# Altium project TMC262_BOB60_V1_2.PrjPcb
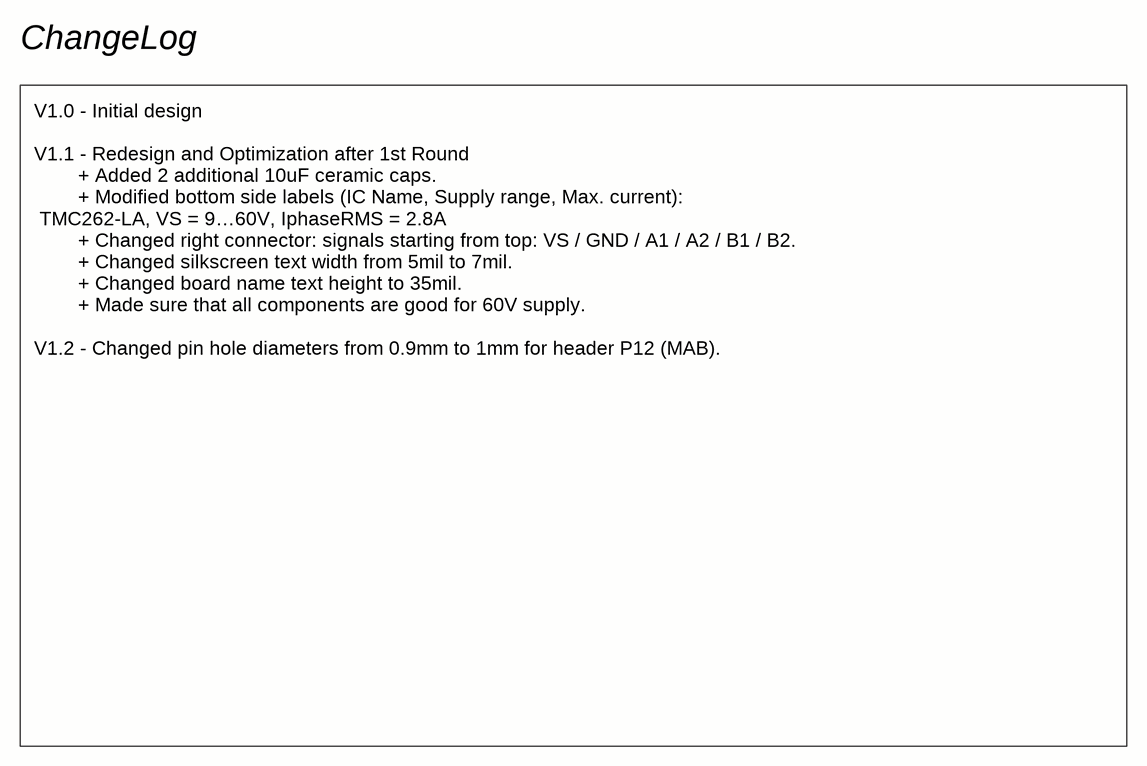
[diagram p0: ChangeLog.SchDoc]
BoardName: TMC262_BOB60; BoardVersion: 1.2; Chip: TMC262-LA; IRMS: 2.8A; VS: 9…60V
2 sheets, 33 parts. Net scope: global (net labels, ports and power ports of the same name join across sheets).
Board file: TMC262_BOB60_V1_2.PcbDoc
Sheets:
  ChangeLog.SchDoc
  TMC262_BOB60_V1_2.SchDoc

## Sheet ChangeLog.SchDoc
size A4

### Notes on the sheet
- ChangeLog
- V1.0 - Initial design
  V1.1 - Redesign and Optimization after 1st Round
  + Added 2 additional 10uF ceramic caps.
  + Modified bottom side labels (IC Name, Supply range, Max. current):
  TMC262-LA, VS = 9…60V, IphaseRMS = 2.8A
  + Changed right connector: signals starting from top: VS / GND / A1 / A2 / B1 / B2.
  + Changed silkscreen text width from 5mil to 7mil.
  + Changed board name text height to 35mil.
  + Made sure that all components are good for 60V supply.
  V1.2 - Changed pin hole diameters from 0.9mm to 1mm for header P12 (MAB).

## Sheet TMC262_BOB60_V1_2.SchDoc
size A4
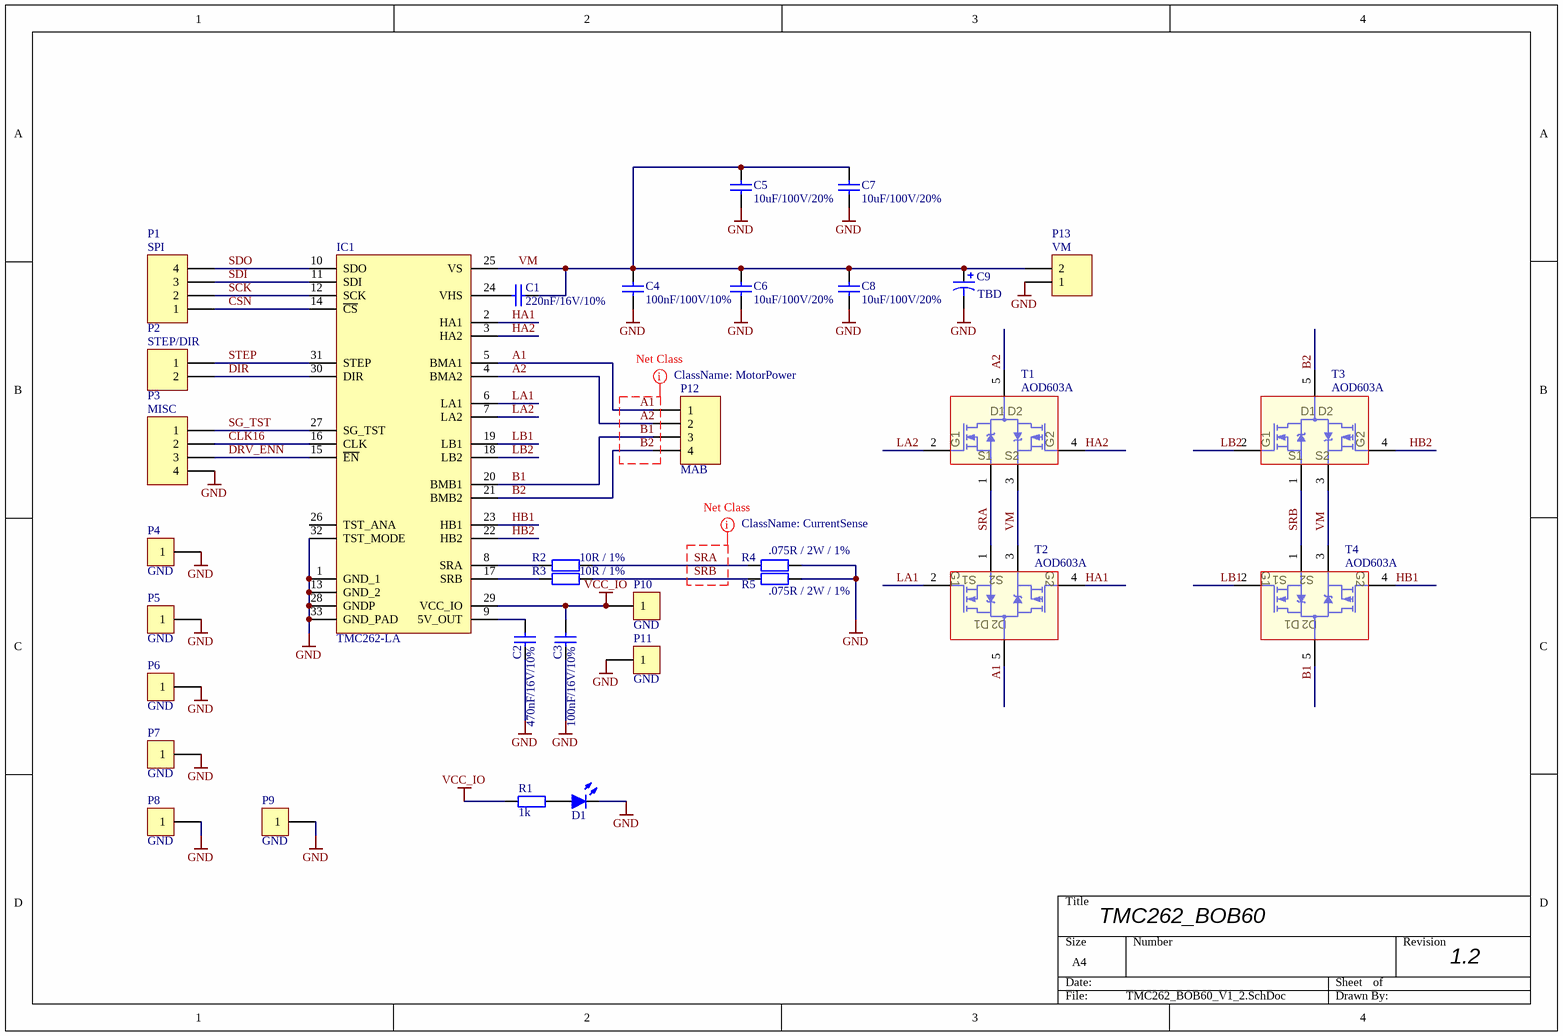
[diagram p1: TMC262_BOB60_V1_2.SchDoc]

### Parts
C1  220nF/16V/10%  [C0603]
C2  470nF/16V/10%  [C0603]
C3  100nF/16V/10%  [C0603]
C4  100nF/100V/10%  [C0603]
C5  10uF/100V/20%  [CKG45NX7S2A106M500JH]
C6  10uF/100V/20%  [CKG45NX7S2A106M500JH]
C7  10uF/100V/20%  [CKG45NX7S2A106M500JH]
C8  10uF/100V/20%  [CKG45NX7S2A106M500JH]
C9  value TBD  [EXT_POL_CAP]  (hidden comment: Cap Pol1)
D1  LED, Blue, SMD, 20mA, 2.8V, 465 nm  [LED_0603]  (value not drawn)
IC1  TMC262-LA  [TMC262_QFN32_0.5_5.0X5.0]
P1  SPI  [4_PIN_THT]
P2  STEP/DIR  [2_PIN_THT]
P3  MISC  [4_PIN_THT]
P4  GND  [TH_PIN]
P5  GND  [TH_PIN]
P6  GND  [TH_PIN]
P7  GND  [TH_PIN]
P8  GND  [TH_PIN]
P9  GND  [TH_PIN]
P10  GND  [TH_PIN]
P11  GND  [TH_PIN]
P12  MAB  [4_PIN_THT_1mm_hole]
P13  VM  [2_PIN_THT]
R1  1k  [R0603]
R2  10R / 1%  [R0603]
R3  10R / 1%  [R0603]
R4  .075R / 2W / 1%  [R2512]
R5  .075R / 2W / 1%  [R2512]
T1  AOD603A  [SOT114P991X239-6N]
T2  AOD603A  [SOT114P991X239-6N]
T3  AOD603A  [SOT114P991X239-6N]
T4  AOD603A  [SOT114P991X239-6N]

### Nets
GND: C2.2 C3.2 C4.1 C5.1 C6.1 C7.1 C8.1 C9.2 D1.2(K) IC1.1(GND_1) IC1.13(GND_2) IC1.28(GNDP) IC1.32(TST_MODE) IC1.33(GND_PAD) P3.4 P4.1 P5.1 P6.1 P7.1 P8.1 P9.1 P11.1 P13.1 R4.1 R5.1
VCC_IO: C3.1 IC1.29(VCC_IO) P10.1 R1.1
A1: IC1.5(BMA1) P12.1 T2.5(D1/D2)
A2: IC1.4(BMA2) P12.2 T1.5(D1/D2)
B1: IC1.20(BMB1) P12.3 T4.5(D1/D2)
B2: IC1.21(BMB2) P12.4 T3.5(D1/D2)
CLK16: IC1.16(CLK) P3.2
CSN: IC1.14(~{CS}) P1.1
DIR: IC1.30(DIR) P2.2
DRV_ENN: IC1.15(~{EN}) P3.3
HA1: IC1.2(HA1) T2.4(G2)
HA2: IC1.3(HA2) T1.4(G2)
HB1: IC1.23(HB1) T4.4(G2)
HB2: IC1.22(HB2) T3.4(G2)
LA1: IC1.6(LA1) T2.2(G1)
LA2: IC1.7(LA2) T1.2(G1)
LB1: IC1.19(LB1) T4.2(G1)
LB2: IC1.18(LB2) T3.2(G1)
SCK: IC1.12(SCK) P1.2
SDI: IC1.11(SDI) P1.3
SDO: IC1.10(SDO) P1.4
SG_TST: IC1.27(SG_TST) P3.1
SRA: R2.1 R4.2 T1.1(S1) T2.1(S1)
SRB: R3.1 R5.2 T3.1(S1) T4.1(S1)
STEP: IC1.31(STEP) P2.1
VM: C1.1 C4.2 C5.2 C6.2 C7.2 C8.2 C9.1 IC1.25(VS) P13.2 T1.3(S2) T2.3(S2) T3.3(S2) T4.3(S2)
NetC1_2: C1.2 IC1.24(VHS)
NetC2_1: C2.1 IC1.9(5V_OUT)
NetD1_1: D1.1(A) R1.2
NetIC1_8: IC1.8(SRA) R2.2
NetIC1_17: IC1.17(SRB) R3.2

Not connected (* = marked no-connect by the designer): IC1 26(TST_ANA)

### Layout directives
net class CurrentSense: SRA, SRB
net class MotorPower: A1, A2, B1, B2

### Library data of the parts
C1 = Capacitor: Ceramic capacitor; MPN: MC0603B224K160CT; Type: MLCC; VoltageRating: 16V; ComponentLinknDescription: Datasheet; MF: Multicomp; Capacitance: 220nF; Precision: 10%
C2 = Capacitor: Ceramic capacitor; MPN: MC0603X474K160CT; Type: MLCC; VoltageRating: 16V; ComponentLinknDescription: Datasheet; MF: Multicomp; Capacitance: 470nF; Precision: 10%
C3 = Capacitor: Ceramic capacitor; MPN: MC0603B104K160CT; Type: MLCC; VoltageRating: 16V; ComponentLinknDescription: Datasheet; MF: Multicomp; Capacitance: 100nF; Precision: 10%
C4 = 0.1 µF, 100 V, ± 10%, X7R, GRM Series: SMD Multilayer Ceramic Capacitor, 0603 [1608 Metric], 0.1 µF, 100 V, ± 10%, X7R, GRM Series; MPN: GRM188R72A104KA35D; Type: MLCC; VoltageRating: 100V; ComponentLinknDescription: Datasheet; MF: MURATA; Capacitance: 100nF
C5-C8 = 10 µF, 100 V, ± 20%, X7S, CKG Series: SMD Multilayer Ceramic Capacitor, 1812 [4532 Metric], 10 µF, 100 V, ± 20%, X7S, CKG Series; Type: MLCC; VoltageRating: 100V; ComponentLinknDescription: Datasheet; MF: TDK; Capacitance: 10uF
C9 = Cap Pol1: Polarized Capacitor (Radial); Fitted: Not fitted
D1 = LED, Blue, SMD, 20mA, 2.8V, 465 nm: MPN: LTST-C191TBKT-5A; MF: Lite-On
IC1 = TMC262-LA: Energy saving high resolution microstepping two phase stepper driver with Step/Dir, SPI, up to 60V, QFN32(5x5); Manufacturer: TRINAMIC; Geometry.Height: 0,9mm; Ordercode - Distri#1: 1460-1044-ND; Ordercode - Distri#2: 1858307
P1 P3 = Header 4: Header, 4-Pin; Fitted: Not fitted
P2 P13 = Header 2: Header, 2-Pin; Fitted: Not fitted
P4-P11 = PIN: Note: n.b; Fitted: Not fitted
P12 = Wire-To-Board Connector, 2.5 mm, 4 Contacts, Header, EH Series, Through Hole, 1 Rows: MPN: B4B-EH-A; MF: JST (JAPAN SOLDERLESS TERMINALS); Fitted: Not fitted
R1 = 1 kohm, 50 V, 0603 [1608 Metric], 63 mW, ± 1%, MC Series: MPN: MC0063W060311K; VoltageRating: 50V; Temp coefficient: *ppm; PowerRating: 63mW; MF: MULTICOMP
R2 R3 = .05 OHM 2W 1% Current Sense Resistor: SMD Chip Resistor, Thick Film, 10 ohm, 50 V, 0603 [1608 Metric], 100 mW, ± 1%, MCWR Series; MPN: MCWR06X10R0FTL; PowerRating: 100mW; ComponentLinknDescription: Datasheet; MF: Multicomp
R4 R5 = .075 OHM 2W 1% Current Sense Resistor: SMD Current Sense Resistor, 0.075 ohm, 2 W, 2512 [6432 Metric], ± 1%, TLR Series; MPN: TLR3A20WR075FTDG; ComponentLinknDescription: Datasheet; MF: TE CONNECTIVITY
T1-T4 = AOD603A: Transistor: N/P-MOSFET; unipolar; complementary; -60/60V; TO252-4; MF: ALPHA & OMEGA SEMICONDUCTOR

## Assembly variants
TMC262_BOB60_V1_1: not fitted C9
